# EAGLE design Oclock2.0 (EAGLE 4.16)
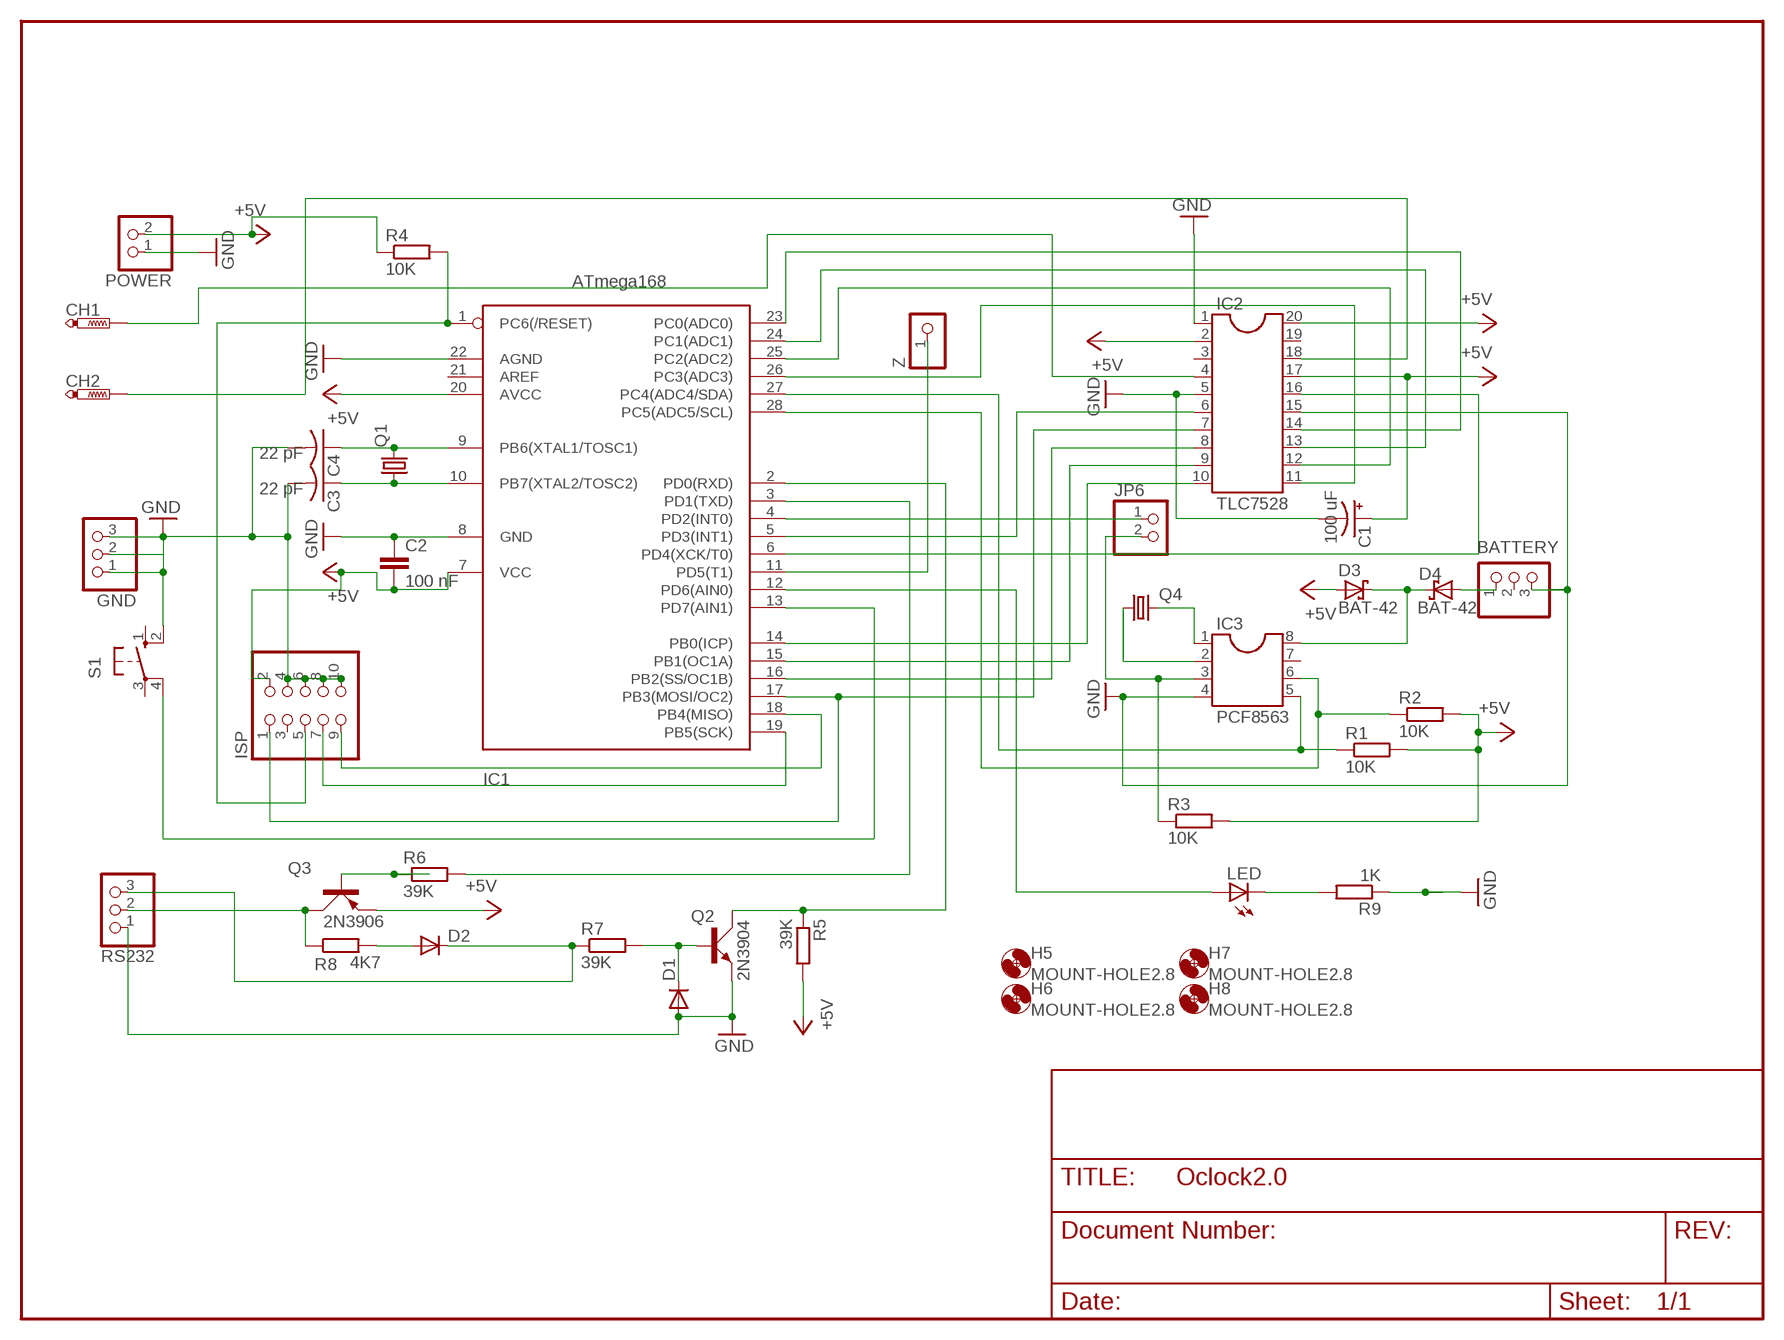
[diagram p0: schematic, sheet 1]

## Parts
BATTERY  PINHD-1X3  [1X03]
C1  100 uF  CPOL-USE2.5-5  [E2,5-5]
C2  100 nF  C-EU050-024X044  [C050-024X044]
C3  22 pF  C-US050-025X075  [C050-025X075]
C4  22 pF  C-US050-025X075  [C050-025X075]
CH1  PTR1PAD1-20Y  [P1-20Y]
CH2  PTR1PAD1-20Y  [P1-20Y]
D1  1N4148  [DO35-10]
D2  1N4148  [DO35-10]
D3  BAT-42  SCHOTTKY-DIODEDO35-7  [DO35-7]
D4  BAT-42  SCHOTTKY-DIODEDO35-7  [DO35-7]
GND  PINHD-1X3  [1X03]
H5  MOUNT-HOLE2.8  [2,8]
H6  MOUNT-HOLE2.8  [2,8]
H7  MOUNT-HOLE2.8  [2,8]
H8  MOUNT-HOLE2.8  [2,8]
IC1  ATmega168  MEGA8-P  [DIL28-3]
IC2  TLC7528  DIL20S  [SOCKED-20]
IC3  PCF8563  DIL8  [DIL08]
ISP  PINHD-2X5  [2X05]
JP6  PINHD-1X2  [1X02]
LED  LED3MM  [LED3MM]
POWER  PINHD-1X2  [1X02]
Q1  CRYSTALHC18U-V  [HC18U-V]
Q2  2N3904  [TO92D]
Q3  2N3906  [TO92D]
Q4  CRYSTALTC26H  [TC26H]
R1  10K  R-EU_0207/10  [0207/10]
R2  10K  R-EU_0207/10  [0207/10]
R3  10K  R-EU_0207/10  [0207/10]
R4  10K  R-EU_0207/10  [0207/10]
R5  39K  R-EU_0207/10  [0207/10]
R6  39K  R-EU_0207/10  [0207/10]
R7  39K  R-EU_0207/10  [0207/10]
R8  4K7  R-EU_0207/10  [0207/10]
R9  1K  R-EU_0207/10  [0207/10]
RS232  PINHD-1X3  [1X03]
S1  10-XX  [B3F-10XX]
Z  PINHD-1X1  [1X01]

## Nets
1PPS-A: IC1.4(PD2(INT0)) JP6.1
1PPS-B: IC3.3 JP6.2 R3.1
+5V: C1.+ C2.2 D3.A IC1.7(VCC) IC1.20(AVCC) IC2.2 IC2.17 IC2.20 ISP.2 POWER.2 Q3.E R1.2 R2.2 R3.2 R4.1 R5.2
BATPOWER: BATTERY.1 D4.A
CH1: CH1.1(TP) IC2.4
CH2: CH2.1(TP) IC2.18
CHSELECT: IC1.5(PD3(INT1)) IC2.6
DACDB0: IC1.23(PC0(ADC0)) IC2.14
DACDB1: IC1.24(PC1(ADC1)) IC2.13
DACDB2: IC1.25(PC2(ADC2)) IC2.12
DACDB3: IC1.26(PC3(ADC3)) IC2.11
DACDB4: IC1.14(PB0(ICP)) IC2.10
DACDB5: IC1.15(PB1(OC1A)) IC2.9
DACDB6: IC1.16(PB2(SS/OC1B)) IC2.8
DACWR: IC1.6(PD4(XCK/T0)) IC2.16
GND: BATTERY.3 C1.- C2.1 C3.2 C4.2 D1.A GND.1 GND.2 GND.3 IC1.8(GND) IC1.22(AGND) IC2.1 IC2.5 IC2.15 IC3.4 ISP.4 ISP.6 ISP.8 ISP.10 POWER.1 Q2.E R9.1 RS232.1 S1.2(S1)
ISPCLOCK: IC1.19(PB5(SCK)) ISP.7
ISPMISO: IC1.18(PB4(MISO)) ISP.9
ISPMOSI-DACDB7: IC1.17(PB3(MOSI/OC2)) IC2.7 ISP.1
LED1LINE: IC1.12(PD6(AIN0)) LED.A
N$11: C4.1 IC1.9(PB6(XTAL1/TOSC1)) Q1.2
N$12: C3.1 IC1.10(PB7(XTAL2/TOSC2)) Q1.1
N$13: IC3.1 Q4.2
N$14: IC3.2 Q4.1
N$24: Q3.B R6.1
N$26: LED.K(C) R9.2
N$27: D1.C Q2.B R7.2
N$30: D2.A R8.2
RESETLINE: IC1.1(PC6(/RESET)) ISP.5 R4.2
RTCPOWER: D3.C D4.C IC3.8
RX-LINE: IC1.2(PD0(RXD)) Q2.C R5.1
RXPC: Q3.C R8.1 RS232.2
SCLLINE: IC1.28(PC5(ADC5/SCL)) IC3.6 R2.1
SDALINE: IC1.27(PC4(ADC4/SDA)) IC3.5 R1.1
SWITCHLINE: IC1.13(PD7(AIN1)) S1.4(P1)
TX-LINE: IC1.3(PD1(TXD)) R6.2
TXPC: D2.C R7.1 RS232.3
ZLINE: IC1.11(PD5(T1)) Z.1
Unconnected: BATTERY.2 IC1.21(AREF) IC2.3 IC2.19 IC3.7 ISP.3 S1.1(S) S1.3(P)

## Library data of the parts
BATTERY GND RS232 = pinhead:PINHD-1X3: PIN HEADER
C1 = rcl:CPOL-US: POLARIZED CAPACITOR, American symbol
C2 = rcl:C-EU: CAPACITOR, European symbol
C3 C4 = rcl:C-US: CAPACITOR, American symbol
CH1 CH2 = testpad:PTR1: TEST PIN
D1 D2 = diode:1N4148: DIODE
D3 D4 = diode:SCHOTTKY-DIODE: Schottky Diode
H5-H8 = holes:MOUNT-HOLE: MOUNTING HOLE with drill center marker
IC1 = atmel:MEGA8-P: MICROCONTROLLER 8 Kbytes FLASH 1 kbytes SRAM 512 bytes EEPROM USART 4-channel 10 bit ADC 2-channel 8 bit ADC Source: avr.lbr
IC2 = ic-package:DIL20: Dual In Line 0.6inch
IC3 = ic-package:DIL8: Dual In Line
ISP = pinhead:PINHD-2X5: PIN HEADER
JP6 POWER = pinhead:PINHD-1X2: PIN HEADER
LED = led:LED: LED
Q1 Q4 = crystal:CRYSTAL: CRYSTAL
Q2 = transistor-small-signal:2N3904: NPN TRANSISTOR
Q3 = transistor-small-signal:2N3906: PNP TRANSISTOR
R1-R9 = rcl:R-EU_: RESISTOR, European symbol
S1 = switch-omron:10-XX: OMRON SWITCH
Z = pinhead:PINHD-1X1: PIN HEADER

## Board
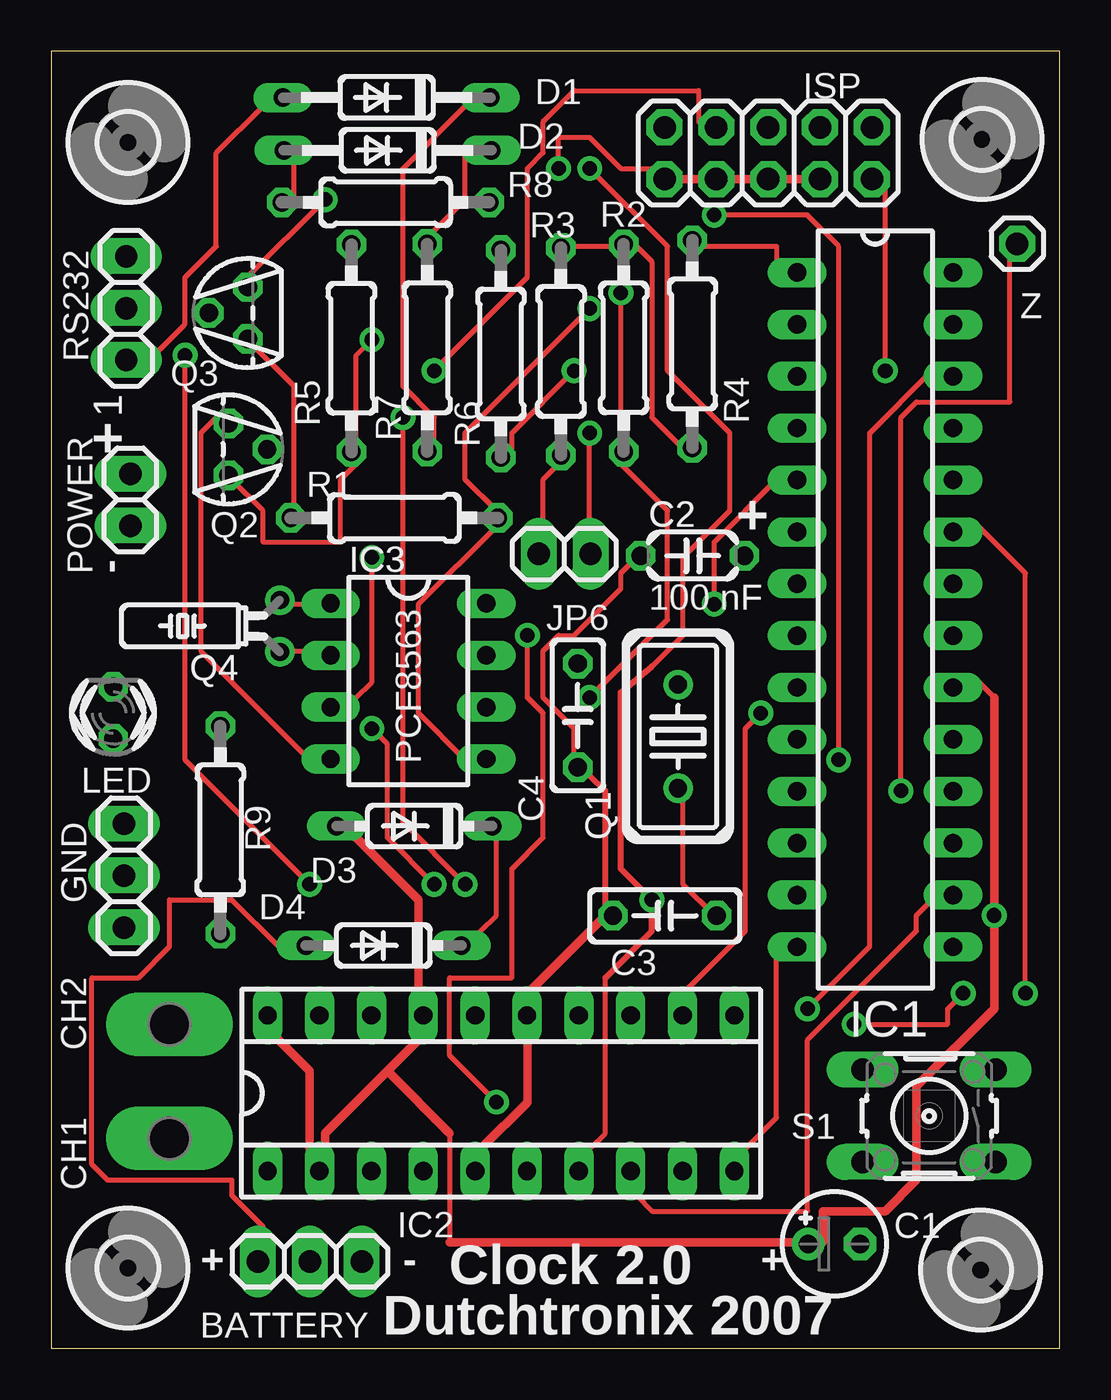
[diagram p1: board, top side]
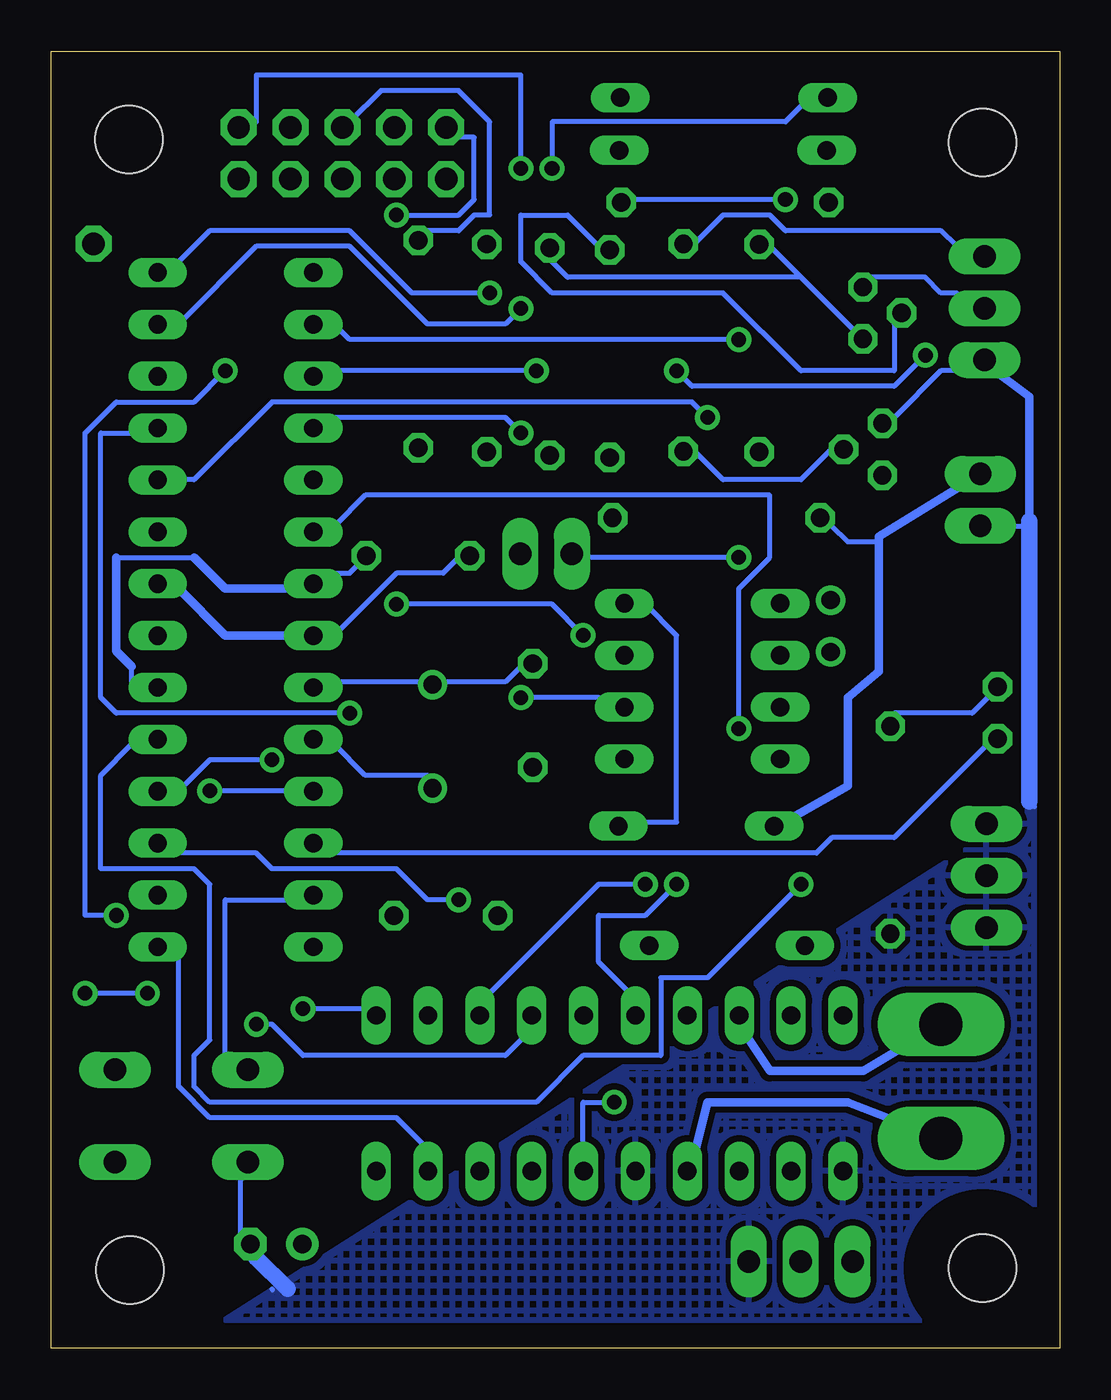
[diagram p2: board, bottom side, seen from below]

Size 49.39 x 63.53 mm. Coordinates in mm from the lower left corner, seen from the top.
Outline: 0,0 49.39,0 49.39,63.53 0,63.53 0,0
Copper layers (1*16): Top 0.035mm / dielectric 1.5mm / Bottom 0.035mm
Design rules "10mils": minimum track width 10mil, minimum drill 28mil, track to track 10mil, track to pad 10mil, pad to pad 10mil, via to via 10mil, smd to smd 10mil, copper to edge 40mil, drill to drill 12mil, minimum pad ring 10mil, minimum via ring 10mil, stop-mask expansion 0mil, vias tented up to drill 0mil, thermal gap 10mil

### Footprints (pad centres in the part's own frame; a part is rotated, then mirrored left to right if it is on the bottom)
1X03 = drill 1.1 long: 1 -2.54,0; 2 0,0; 3 2.54,0
E2,5-5 = drill 0.9 pad 1.6 round: + -1.27,0 | drill 0.9 pad 1.6 octagon: - 1.27,0
C050-024X044 = drill 0.9 octagon: 1 -2.54,0; 2 2.54,0
C050-025X075 = drill 0.9 octagon: 1 -2.54,0; 2 2.54,0
P1-20Y = drill 2.1 pad 2.54 long: 1 0,0
DO35-10 = drill 0.9 long: A 5.08,0; C -5.08,0
DO35-7 = drill 0.9 long: A 3.81,0; C -3.81,0
2,8 = hole 3.3: 0,0
DIL28-3 = drill 0.9 long: 1 -16.51,-3.81; 2 -13.97,-3.81; 3 -11.43,-3.81; 4 -8.89,-3.81; 5 -6.35,-3.81; 6 -3.81,-3.81; 7 -1.27,-3.81; 8 1.27,-3.81; 9 3.81,-3.81; 10 6.35,-3.81; 11 8.89,-3.81; 12 11.43,-3.81; 13 13.97,-3.81; 14 16.51,-3.81; 15 16.51,3.81; 16 13.97,3.81; 17 11.43,3.81; 18 8.89,3.81; 19 6.35,3.81; 20 3.81,3.81; 21 1.27,3.81; 22 -1.27,3.81; 23 -3.81,3.81; 24 -6.35,3.81; 25 -8.89,3.81; 26 -11.43,3.81; 27 -13.97,3.81; 28 -16.51,3.81
SOCKED-20 = drill 0.9 long: 1 -11.43,-3.81; 2 -8.89,-3.81; 3 -6.35,-3.81; 4 -3.81,-3.81; 5 -1.27,-3.81; 6 1.27,-3.81; 7 3.81,-3.81; 8 6.35,-3.81; 9 8.89,-3.81; 10 11.43,-3.81; 11 11.43,3.81; 12 8.89,3.81; 13 6.35,3.81; 14 3.81,3.81; 15 1.27,3.81; 16 -1.27,3.81; 17 -3.81,3.81; 18 -6.35,3.81; 19 -8.89,3.81; 20 -11.43,3.81
DIL08 = drill 0.9 long: 1 -3.81,-3.81; 2 -1.27,-3.81; 3 1.27,-3.81; 4 3.81,-3.81; 5 3.81,3.81; 6 1.27,3.81; 7 -1.27,3.81; 8 -3.81,3.81
2X05 = drill 1.1 octagon: 1 -5.08,-1.27; 2 -5.08,1.27; 3 -2.54,-1.27; 4 -2.54,1.27; 5 0,-1.27; 6 0,1.27; 7 2.54,-1.27; 8 2.54,1.27; 9 5.08,-1.27; 10 5.08,1.27
1X02 = drill 1.1 long: 1 -1.27,0; 2 1.27,0
LED3MM = drill 0.9 octagon: A -1.27,0; K 1.27,0
HC18U-V = drill 0.9 round: 1 -2.54,0; 2 2.54,0
TO92D = drill 0.9 octagon: B 0,1.905; C 1.27,0; E -1.27,0
TC26H = drill 0.9 round: 1 -1.27,0; 2 1.27,0
0207/10 = drill 0.9 octagon: 1 -5.08,0; 2 5.08,0
B3F-10XX = drill 1.1 long: 1 -3.251,2.261; 2 3.251,2.261; 3 -3.251,-2.261; 4 3.251,-2.261
1X01 = drill 1.1 octagon: 1 0,0

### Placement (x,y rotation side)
BATTERY  12.68,4.26 0 top
C1  38.35,5.12 0 top
C2  31.41,38.82 0 top
C3  30.06,21.18 180 top
C4  25.79,31 270 top
CH1  5.8,10.28 270 top
CH2  5.8,15.87 270 top
D1  16.43,61.25 180 top
D2  16.48,58.66 180 top
D3  17.79,25.58 180 top
D4  16.28,19.72 180 top
GND  3.58,23.15 90 top
H5  3.77,59.05 0 top
H6  3.77,3.93 0 top
H7  45.52,3.84 0 top
H8  45.58,59.2 0 top
IC1  40.35,36.17 270 top
IC2  22.04,12.5 0 top
IC3  17.5,32.67 270 top
ISP  35.12,58.53 180 top
JP6  25.15,38.9 180 top
LED  3.04,31.13 90 top
POWER  3.88,41.56 90 top
Q1  30.7,29.97 90 top
Q2  8.68,44.02 270 top
Q3  9.63,50.7 90 top
Q4  11.2,35.37 90 top
R1  16.81,40.66 180 top
R2  28.04,48.99 90 top
R3  24.97,48.81 90 top
R4  31.4,49.18 90 top
R5  14.71,48.97 90 top
R6  22.03,48.7 270 top
R7  18.42,49 270 top
R8  16.38,56.12 180 top
R9  8.29,25.39 90 top
RS232  3.68,50.94 90 top
S1  43,11.39 180 top
Z  47.31,54.1 0 top

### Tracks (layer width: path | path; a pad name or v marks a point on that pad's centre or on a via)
1PPS-A  (via drill 0.71)
  Top 0.254: v26.38,44.83 26.38,40.25 JP6.1
  Bottom 0.254: v26.38,44.83 27.14,45.59 35.52,45.59 IC1.4
1PPS-B  (via drill 0.71)
  Top 0.254: v15.71,38.73 15.71,32.63 14.95,31.87 IC3.3 | R3.1 24.85,43.3 24.09,42.54 24.09,40.25 JP6.2
  Bottom 0.254: v15.71,38.73 23.33,38.73 JP6.2
+5V  (via drill 0.71)
  Top 0.254: R3.2 25.62,53.97 27.9,53.97 R2.2 28.66,53.97 29.43,53.21 29.43,45.59 30.95,44.06 R4.1 | 19.52,10.54 19.52,5.2 | 36.28,5.2 C1.+ | 46.19,31.87 45.43,32.63 IC1.20 | v40.86,47.87 40.86,57.02 ISP.2 | 13.42,9.77 IC2.2 12.66,9.77 | Q3.E 9.61,49.4 11.9,47.11 11.9,41.02 R1.2
  Top 0.406: 12.66,9.77 12.66,13.58 11.14,15.11 IC2.20 | 16.47,13.58 13.42,10.54 13.42,9.77 | 16.47,13.58 18,15.11 IC2.17 18,17.39 18,21.97 14.95,25.01 D3.A | 16.47,13.58 19.52,10.54 | 19.52,5.2 36.28,5.2 | 46.19,31.87 v46.19,21.2 46.19,16.63 42.38,12.82 42.38,8.25 40.86,6.73 37.81,6.73 37.81,5.2 C1.+
  Bottom 0.254: 12.66,52.45 14.19,53.97 R5.2 | 12.66,52.45 9.61,49.4 Q3.E | 12.66,52.45 24.09,52.45 24.85,53.21 R3.2 | 45.43,33.4 45.43,32.63 IC1.20 | 46.19,38.73 42.38,38.73 | 37.81,37.21 IC1.7 35.52,37.97 34.76,37.97 34,38.73 C2.2 | v40.86,47.87 42.38,46.35 46.19,46.35 47.71,44.83 47.71,21.2 v46.19,21.2 | 8.85,39.49 10.38,39.49 11.14,40.25 R1.2
  Bottom 0.406: 45.43,33.4 46.19,34.16 46.19,38.73 | 42.38,38.73 40.86,37.21 37.81,37.21 | POWER.2 8.85,39.75 8.85,39.49 8.85,33.14 10.38,31.87 10.38,27.55 13.93,25.52 D3.A
BATPOWER
  Top 0.254: D4.A 11.14,19.68 8.85,21.97 5.8,21.97 5.8,19.68 4.28,18.16 1.99,18.16 1.99,9.01 2.76,8.25 8.85,8.25 8.85,7.49 10.38,5.96 BATTERY.1
CH1
  Bottom 0.406: CH1.1 10.38,12.06 17.23,12.06 18,9.01 IC2.4
CH2
  Bottom 0.406: CH2.1 9.61,13.58 14.19,13.58 15.71,15.87 IC2.18
CHSELECT  (via drill 0.71)
  Top 0.254: v23.33,34.92 23.33,31.87 24.09,31.11 24.09,25.01 22.57,23.49 22.57,18.16 19.52,18.16 19.52,14.35 v21.81,12.06 | v32.47,36.44 32.47,39.49 35.52,42.54 IC1.5
  Bottom 0.254: v23.33,34.92 24.85,36.44 v32.47,36.44 | v21.81,12.06 23.33,12.06 23.33,9.77 IC2.6
DACDB0  (via drill 0.71)
  Top 0.254: v39.33,15.87 43.9,15.87 43.9,16.63 v44.67,17.39 | v47.71,17.39 47.71,37.97 45.43,40.25 IC1.23
  Bottom 0.254: v44.67,17.39 v47.71,17.39 | v39.33,15.87 38.57,15.87 37.05,14.35 27.14,14.35 26.38,15.11 IC2.14
DACDB1  (via drill 0.71)
  Top 0.254: v20.28,22.73 17.23,25.78 v17.23,45.59
  Bottom 0.254: v20.28,22.73 22.57,22.73 27.9,17.39 IC2.13 | v17.23,45.59 18,46.35 38.57,46.35 42.38,42.54 43.14,42.54 IC1.24
DACDB2  (via drill 0.71)
  Top 0.254: v34.76,31.11 34,30.35 34,20.44 30.95,17.39 IC2.12
  Bottom 0.254: v34.76,31.11 46.19,31.11 46.95,31.87 46.95,44.83 45.43,44.83 IC1.25
DACDB3  (via drill 0.71)
  Top 0.254: v37.05,16.63 40.09,19.68 40.09,44.83 43.14,47.87 IC1.26
  Bottom 0.254: v37.05,16.63 34,16.63 IC2.11
DACDB4
  Top 0.254: IC2.10 34,9.77 35.52,11.3 35.52,19.68 IC1.14
DACDB5
  Bottom 0.254: IC2.9 30.95,9.77 32.47,11.3 41.62,11.3 43.14,12.82 43.14,19.68 IC1.15
DACDB6
  Top 0.254: IC2.8 28.66,7.49 29.43,6.73 37.05,6.73 37.05,15.11 42.38,20.44 42.38,21.2 43.14,21.97 IC1.16
DACWR  (via drill 0.71)
  Top 0.254: v18.76,22.73 16.47,25.01 16.47,29.59 v15.71,30.35
  Bottom 0.254: v18.76,22.73 20.28,21.2 22.57,21.2 22.57,18.92 21.04,17.39 IC2.16 | v15.71,30.35 15.71,37.21 14.19,38.73 14.19,41.78 34,41.78 35.52,40.25 IC1.6
GND  (via drill 0.71)
  Top 0.254: 26.38,28.06 C4.2 25.62,28.82 25.62,30.35 24.09,31.87 24.09,34.16 24.85,34.92 25.62,34.92 27.9,37.21 27.9,37.97 28.66,38.73 C2.1 | D1.A 10.38,60.83 8.09,58.54 8.09,53.97 6.57,52.45 6.57,50.16 5.04,48.64 RS232.1 | v24.85,57.78 24.85,59.3 26.38,59.3 27.9,57.78 29.43,57.78 ISP.10 | IC3.4 12.66,28.82 7.33,34.16 7.33,44.83 8.09,45.59 Q2.E
  Top 0.305: 26.38,28.06 27.14,27.3 27.14,21.2
  Top 0.406: C3.2 27.14,21.2 23.33,17.39 IC2.15 23.33,15.11 23.33,12.06 21.04,9.77 IC2.5 | 37.81,57.26 ISP.4 | ISP.10 ISP.8 ISP.6 37.05,57.26 | 37.05,57.26 37.81,57.26 | 37.81,57.26 37.81,57.02 | 37.05,57.26 37.05,57.02
  Bottom 0.254: 37.81,34.92 IC1.8 35.52,34.92 32.47,37.97 30.19,37.97 29.43,38.73 C2.1 | 43.14,37.21 IC1.22 | v24.85,57.78 24.85,60.07 13.42,60.07 12.66,60.83 D1.A | S1.2 40.09,8.25 40.09,5.2 C1.- 39.33,4.44 | Q2.E 8.09,45.59 5.8,47.87 5.04,47.87 RS232.1 | 1.49,40.51 1.23,40.25 1.49,40.25 2.76,40.25 POWER.1 | 1.23,26.54 1.49,26.79 | 38.54,2.86 38.57,2.92
  Bottom 0.406: 43.14,37.21 40.86,34.92 37.81,34.92 | 1.49,40.51 1.49,46.6 3.52,48.13 RS232.1
  Bottom 0.61: GND.3 3.52,25.78
  Bottom 0.813: 1.49,26.79 1.49,40.25 1.49,40.51 | 37.81,2.92 39.33,4.44
  pour Bottom (isolate 0.305, hatched): 1.23,26.54 40.86,1.39 1.23,1.39
ISPCLOCK  (via drill 0.71)
  Top 0.254: v18.76,47.87 23.33,52.45 23.33,57.78 24.09,58.54 24.09,60.07 25.62,61.59 31.71,61.59 31.71,60.07 ISP.7 | v6.57,48.64 6.57,28.82 v12.66,22.73
  Bottom 0.254: v12.66,22.73 17.23,18.16 19.52,18.16 19.52,14.35 23.33,14.35 25.62,12.06 41.62,12.06 42.38,12.82 42.38,14.35 41.62,15.11 41.62,22.73 42.38,23.49 46.95,23.49 46.95,28.06 45.43,29.59 IC1.19 | v6.57,48.64 8.09,47.11 18,47.11 v18.76,47.87
ISPMISO  (via drill 0.71)
  Top 0.254: v38.57,28.82 38.57,53.97 37.05,55.49 v32.47,55.49
  Bottom 0.254: v38.57,28.82 41.62,28.82 43.14,27.3 IC1.18 | v32.47,55.49 29.43,55.49 28.66,56.26 28.66,59.3 29.43,59.3 ISP.9
ISPMOSI-DACDB7  (via drill 0.71)
  Top 0.254: 27.14,18.16 27.14,10.54 26.38,9.77 IC2.7 | v26.38,57.78 30.19,53.97 30.19,47.87 33.24,44.83 33.24,41.02 30.95,38.73 30.95,34.92 29.43,33.4
  Top 0.305: 29.43,33.4 27.9,32.13 27.9,23.49 v29.43,21.97 29.43,20.44 27.14,18.16
  Bottom 0.254: v26.38,57.78 26.38,62.35 39.33,62.35 39.33,60.07 ISP.1 | v29.43,21.97 30.95,21.97 32.47,23.49 38.57,23.49 39.33,24.25 43.14,24.25 IC1.17
LED1LINE
  Bottom 0.254: LED.A 3.52,29.59 8.09,25.01 11.14,25.01 11.9,24.25 35.52,24.25 IC1.12
N$11
  Bottom 0.254: IC1.9 35.52,32.63 30.95,32.63 Q1.2 30.19,32.63 27.14,32.63 26.38,33.4 C4.1
N$12
  Top 0.254: C3.1 32.47,21.2 30.95,22.73 30.95,27.3 Q1.1
  Bottom 0.254: IC1.10 35.52,29.59 34,28.06 30.95,28.06 Q1.1
N$13
  Top 0.254: IC3.1 12.66,36.44 11.9,36.44 Q4.2
N$14
  Top 0.254: IC3.2 12.66,34.16 11.9,34.16 Q4.1
N$24
  Bottom 0.254: Q3.B 8.09,50.16 8.09,47.87 12.66,47.87 16.47,51.68 24.85,51.68 26.38,53.21 26.38,55.49 24.09,55.49 22.57,53.97 R6.1
N$26
  Bottom 0.254: LED.K 3.52,31.87 4.28,31.11 8.09,31.11 R9.2
N$27
  Top 0.254: D1.C 20.28,60.83 17.23,57.78 17.23,47.11 18.76,45.59 18.76,44.06 R7.2
  Bottom 0.254: Q2.B 11.14,44.06 12.66,42.54 16.47,42.54 18,44.06 R7.2
N$30
  Top 0.254: R8.2 11.9,56.26 11.9,58.54 D2.A
RESETLINE
  Top 0.254: R4.2 31.71,53.97 35.52,53.97 35.52,53.21 IC1.1
  Bottom 0.254: ISP.5 34.76,60.07 33.24,61.59 29.43,61.59 27.9,60.07 27.9,55.49 28.66,55.49 29.43,54.73 30.95,54.73 R4.2
RTCPOWER
  Top 0.254: D4.C 21.04,20.44 21.81,21.2 21.81,25.01 D3.C
  Bottom 0.254: IC3.8 20.28,36.44 18.76,34.92 18.76,25.78 20.28,25.78 D3.C
RX-LINE  (via drill 0.71)
  Top 0.254: Q2.C 8.85,42.54 10.38,41.02 10.38,39.49 14.19,39.49 14.19,42.54 14.95,43.3 R5.1 14.95,44.06 14.95,48.64 v15.71,49.4
  Bottom 0.254: v15.71,49.4 34.76,49.4 35.52,50.16 IC1.2
RXPC  (via drill 0.71)
  Top 0.254: v13.42,56.26 9.61,52.45 Q3.C
  Bottom 0.254: Q3.C 9.61,52.45 6.57,52.45 5.8,51.68 5.04,51.68 RS232.2 | v13.42,56.26 21.04,56.26 R8.1
SCLLINE  (via drill 0.71)
  Top 0.254: v26.38,31.87 30.19,35.68 30.19,41.02 27.9,43.3 R2.1 27.9,44.06 v27.9,51.68
  Bottom 0.254: v26.38,31.87 22.57,31.87 IC3.6 | v27.9,51.68 31.71,51.68 34.76,54.73 41.62,54.73 43.14,53.21 IC1.28
SDALINE  (via drill 0.71)
  Top 0.254: IC3.5 20.28,28.82 18,31.11 18,36.44 21.81,40.25 R1.1 21.81,41.02 20.28,42.54 20.28,44.83 v26.38,50.92
  Bottom 0.254: v26.38,50.92 27.14,50.16 30.95,50.16 34.76,53.97 39.33,53.97 43.14,50.16 IC1.27
SWITCHLINE
  Bottom 0.254: S1.4 40.86,14.35 40.86,21.97 37.81,21.97 IC1.13
TX-LINE  (via drill 0.71)
  Top 0.254: v25.62,47.87 22.57,44.83 22.57,44.06 R6.2
  Bottom 0.254: v25.62,47.87 35.52,47.87 IC1.3
TXPC
  Top 0.254: R7.1 18.76,54.73 20.28,56.26 20.28,58.54 D2.C
  Bottom 0.254: RS232.3 5.04,53.97 5.8,54.73 13.42,54.73 14.19,55.49 16.47,55.49 18,53.97 R7.1
ZLINE  (via drill 0.71)
  Top 0.254: v41.62,27.3 41.62,45.59 42.38,46.35 46.95,46.35 46.95,53.97 Z.1
  Bottom 0.254: v41.62,27.3 37.81,27.3 IC1.11

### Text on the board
tNames: 1 | + | C2 | + | - | IC3 | PCF8563 | 100 nF | Q4 | Q1 | + | - | + | Clock 2.0 | Dutchtronix 2007
tValues: -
